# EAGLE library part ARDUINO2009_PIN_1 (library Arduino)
The Arduino Duemilanove ("2009") is a microcontroller board based on the ATmega168 or ATmega328. - 14 digital input/output pins (of which 6 can be used as PWM outputs) - 6 analog inputs, a 16 MHz crystal oscillator - USB connection - power jack - ISP header - reset button It contains everything needed to support the microcontroller; simply connect it to a computer with a USB cable or power it with a AC-to-DC adapter or battery to get started http://arduino.cc/en/Main/ArduinoBoardDuemilanove
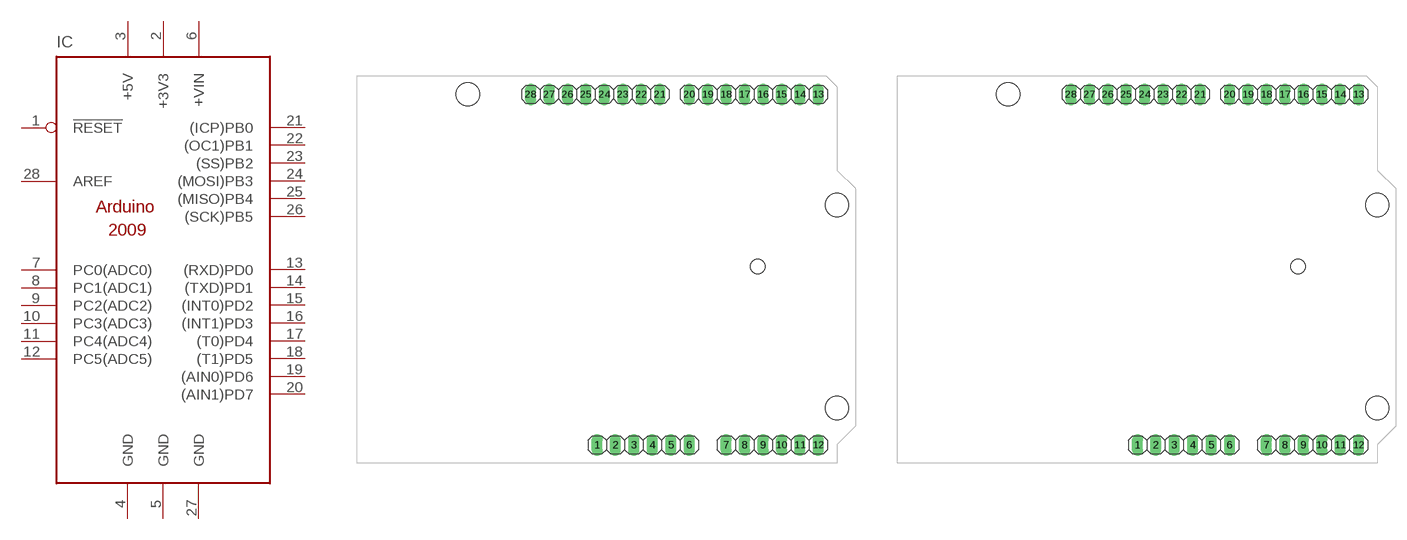
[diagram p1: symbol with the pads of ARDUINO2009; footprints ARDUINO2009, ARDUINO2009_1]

Designator prefix IC

## ARDUINO2009_PIN_10  [ARDUINO2009]
1  !RESET
2  +3V3  pwr
3  +5V  pwr
4  GND  pwr
5  GND  pwr
6  +VIN
7  PC0(ADC0)
8  PC1(ADC1)
9  PC2(ADC2)
10  PC3(ADC3)
11  PC4(ADC4)
12  PC5(ADC5)
13  (RXD)PD0
14  (TXD)PD1
15  (INT0)PD2
16  (INT1)PD3
17  (T0)PD4
18  (T1)PD5
19  (AIN0)PD6
20  (AIN1)PD7
21  (ICP)PB0
22  (OC1)PB1
23  (SS)PB2
24  (MOSI)PB3
25  (MISO)PB4
26  (SCK)PB5
27  GND  pwr
28  AREF

## ARDUINO2009_PIN_11  [ARDUINO2009_1]
Pads as for ARDUINO2009

## ARDUINO2009_PIN_12  [ARDUINO2009_2]
Pads as for ARDUINO2009

## Footprint ARDUINO2009 (pad centres in mm)
drill 1.016 long: 1 33.02,2.54; 2 35.56,2.54; 3 38.1,2.54; 4 40.64,2.54; 5 43.18,2.54; 6 45.72,2.54; 7 50.8,2.54; 8 53.34,2.54; 9 55.88,2.54; 10 58.42,2.54; 11 60.96,2.54; 12 63.5,2.54; 13 63.5,50.8; 14 60.96,50.8; 15 58.42,50.8; 16 55.88,50.8; 17 53.34,50.8; 18 50.8,50.8; 19 48.26,50.8; 20 45.72,50.8; 21 41.656,50.8; 22 39.116,50.8; 23 36.576,50.8; 24 34.036,50.8; 25 31.496,50.8; 26 28.956,50.8; 27 26.416,50.8; 28 23.876,50.8
hole 3.2 at 15.24,50.8
hole 3.2 at 66.04,35.56
hole 3.2 at 66.04,7.62
hole 2 at 55.17,27.114

## Footprint ARDUINO2009_1 (pad centres in mm)
drill 1.016 long: 1 33.02,2.54; 2 35.56,2.54; 3 38.1,2.54; 4 40.64,2.54; 5 43.18,2.54; 6 45.72,2.54; 7 50.8,2.54; 8 53.34,2.54; 9 55.88,2.54; 10 58.42,2.54; 11 60.96,2.54; 12 63.5,2.54; 13 63.5,50.8; 14 60.96,50.8; 15 58.42,50.8; 16 55.88,50.8; 17 53.34,50.8; 18 50.8,50.8; 19 48.26,50.8; 20 45.72,50.8; 21 41.656,50.8; 22 39.116,50.8; 23 36.576,50.8; 24 34.036,50.8; 25 31.496,50.8; 26 28.956,50.8; 27 26.416,50.8; 28 23.876,50.8
hole 3.2 at 15.24,50.8
hole 3.2 at 66.04,35.56
hole 3.2 at 66.04,7.62
hole 2 at 55.17,27.114

## Footprint ARDUINO2009_2 (pad centres in mm)
drill 1.016 long: 1 33.02,2.54; 2 35.56,2.54; 3 38.1,2.54; 4 40.64,2.54; 5 43.18,2.54; 6 45.72,2.54; 7 50.8,2.54; 8 53.34,2.54; 9 55.88,2.54; 10 58.42,2.54; 11 60.96,2.54; 12 63.5,2.54; 13 63.5,50.8; 14 60.96,50.8; 15 58.42,50.8; 16 55.88,50.8; 17 53.34,50.8; 18 50.8,50.8; 19 48.26,50.8; 20 45.72,50.8; 21 41.656,50.8; 22 39.116,50.8; 23 36.576,50.8; 24 34.036,50.8; 25 31.496,50.8; 26 28.956,50.8; 27 26.416,50.8; 28 23.876,50.8
hole 3.2 at 15.24,50.8
hole 3.2 at 66.04,35.56
hole 3.2 at 66.04,7.62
